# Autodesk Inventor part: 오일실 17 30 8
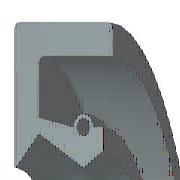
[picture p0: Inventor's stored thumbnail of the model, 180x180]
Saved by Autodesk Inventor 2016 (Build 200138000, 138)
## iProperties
Created: 2012-02
Part Number: 오일실 17 30 8
Material: 고무
Description: 오일-실
Document SubType Name: Modeling
Standard: KS B 2804
Designer: mduedu
Standards Organization: KS
Language: ko-KR
Size Designation: D - 17 30 8
Categories: <MemberInstance><Categories><Category DisplayName="샤프트 부품" InternalName="7f7aeb1f-a693-4053-b835-cee3144e0d98" Mnemonic="SHFT"><Category DisplayName="실링" Intern
Density: 0.93 g/cm^3
Appearance: 고무 - 검은색 - 버전 1.1
IsCustomPart: 1
Author: mduedu
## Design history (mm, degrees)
revolve "본체" stored, may be unused: angle "d17" = 90 deg
revolve "스프링1" stored, may be unused: angle "d18" = 90 deg
body "Solid1"
sketch "스케치1"
  geometry: L1 (0, 15)-(8, 15); L2 (8, 13.25)-(1.75, 13.25); L3 (1.75, 10.25)-(4.9, 8.5); L4 (4.9, 8.5)-(0, 8.5); L5 (0, 0)-(9.586, 0) reference; L6 (4.9, 8.5)-(6.3, 9.375); L7 (0, 18)-(0, -3) reference; L8 (-1.941, 0)-(11.507, 0) reference; L9 (4.2, 10.6)-(1.75, 11.21); L10 (1.75, 11.21)-(1.75, 13.25); L11 (0, 15)-(0, 8.588); L12 (4.9, 8.5)-(0, 8.5); L13 (1.75, 10.25)-(0.152, 8.528); L14 (8, 15)-(8, 13.25); L15 (5.6, 10.6)-(6.3, 10.6); L16 (6.3, 10.6)-(6.3, 9.375); C1 r 0.455 at (4.9, 10.6); A1 r 0.7 centre (4.9, 10.6) between (5.6, 10.6) and (4.2, 10.6); A2 r 0.088 centre (0.088, 8.588) between (0, 8.588) and (0.152, 8.528); 1 further point
  constraints: 28 end point, 5 horizontal alignment, 5 point on line, 4 point on circle, 4 vertical alignment, 3 centre point, 3 tangent, 2 collinear, 2 horizontal, 2 perpendicular, 1 coincident, 1 parallel
  dimensions: "d0" = 30 diameter of L1 L5 (= SD2); "d1" = 1.75 distance of L1.end L2.start (= SD); "d2" = 0.91 diameter of C1 (= SPDI); "d3" = 1.4 diameter of A1 (= SPDA); "d4" = 17 diameter of L3.end L5 (= NND); "d5" = 20.5 diameter of L3.start L5 (= TKDM); "d7" = 22.42 diameter of L9.end L5 (= TKDM + 0.24 x SWDT); "d8" = 1.75 distance between parallel lines of L11 L10 (= SD); "d9" = 4.9 distance from line of L11 C1.centre (= SPDST); "d10" = 21.2 diameter of C1.centre L5 (= HLDM); "d11" = 0.0875 radius of A2 (= 0.25 x LAB); "d12" = 6.3 distance between parallel lines of L11 L16 (= SDI); "d13" = 18.75 diameter of L6.end L5 (= ABDM); "d14" = 8 distance from line of L11 L1.end (= SWDT)
fillet "모깎기1" dims "d6" = 0.3 (= RR)
other parameters: "SD2" = 30 [user parameter; used in 1 equation term], "SWDT" = 8 [user parameter; used in 2 equation terms], "RR" = 0.3 [user parameter; used in 1 equation term], "SD" = 1.75 [user parameter; used in 2 equation terms], "NND" = 17 [user parameter; used in 1 equation term], "SPDA" = 1.4 [user parameter; used in 1 equation term], "SPDI" = 0.91 [user parameter; used in 1 equation term], "TKDM" = 20.5 [user parameter; used in 2 equation terms], "HLDM" = 21.2 [user parameter; used in 1 equation term], "ABDM" = 18.75 [user parameter; used in 1 equation term], "SDI" = 6.3 [user parameter; used in 1 equation term], "SPDST" = 4.9 [user parameter; used in 1 equation term], "LAB" = 0.35 [user parameter; used in 1 equation term], "d15" = 0, "d16" = 0, "d19" = 0
